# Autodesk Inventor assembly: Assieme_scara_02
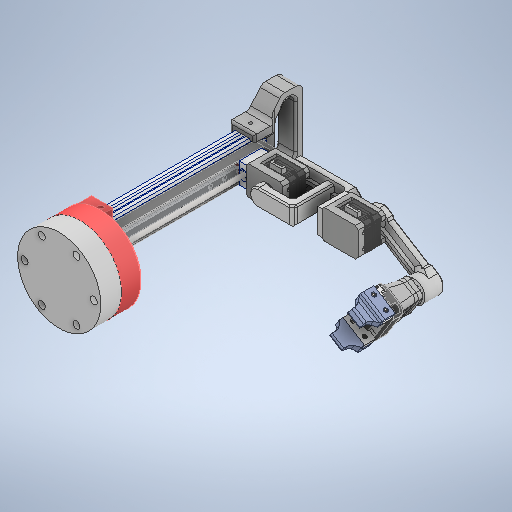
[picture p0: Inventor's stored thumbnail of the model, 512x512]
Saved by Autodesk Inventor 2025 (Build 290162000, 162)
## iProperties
Created: 2025-11
Part Number: Assieme_scara_02
Document SubType Name: Assembly
Designer: Ryzen5700u
Title: Assieme_scara_03.stp
Author: R5800u
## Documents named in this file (17)
- C:\Users\Ryzen5700u\Desktop\scara_06\Assieme_scara_05.iam
- C:\Users\Ryzen5700u\Desktop\scara_06\base1.ipt
- C:\Users\Ryzen5700u\Desktop\scara_06\blocco_motore1.ipt
- C:\Users\Ryzen5700u\Desktop\scara_06\AS 1420 - 1973 - M4 x 30.ipt
- C:\Users\Ryzen5700u\Desktop\scara_06\tslot 2040.ipt
- C:\Users\Ryzen5700u\Desktop\scara_06\Assieme_profilato.iam
- C:\Users\Ryzen5700u\Desktop\scara_06\maniglia.ipt
- C:\Users\Ryzen5700u\Desktop\scara_06\disco_120.ipt
- C:\Users\Ryzen5700u\Desktop\scara_06\gripper v3.iam
- C:\Users\Ryzen5700u\Desktop\scara_06\nema17_23mm.ipt
- C:\Users\Ryzen5700u\Desktop\scara_06\braccio_nema17.ipt
- C:\Users\Ryzen5700u\Desktop\scara_06\blocco_motore2.ipt
- C:\Users\Ryzen5700u\Desktop\scara_06\braccio_2_nema17.ipt
- C:\Users\Ryzen5700u\Desktop\scara_06\DUOPAN-DG.ipt
- C:\Users\Ryzen5700u\Documents\Inventor\Content Center Files\R2025\it-IT\BS 290 SKF(30)\BS 290 SKF - SKF 618_8.ipt
- C:\Users\Ryzen5700u\Desktop\scara_06\blocco_braccio_01.ipt
- C:\Users\Ryzen5700u\Documents\Inventor\Content Center Files\R2025\it-IT\ISO 14580_2011(E)\ISO 14580 M2,5x12-4.8.ipt
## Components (22 placed, 16 different names)
1. base1:1
2. blocco_motore1:1
3. AS 1420 - Metrico M4 x 30:1
4. AS 1420 - Metrico M4 x 30:2
5. AS 1420 - Metrico M4 x 30:3
6. AS 1420 - Metrico M4 x 30:4
7. tslot 2040:1 — Angolo:5
8. Assieme_profilato:1 [sub-assembly] — Coincidente:3, Angolo:1, Coincidente:4, Angolo:2
9. maniglia:1
10. disco_120:1
11. gripper v3:1 [sub-assembly] — Rotazionale:3, Angolo:3
12. nema17_23mm:1 — Coincidente:5, Allineato:1, Coincidente:6, Rotazionale:1
13. braccio_nema17:1
14. blocco_motore2:1 — Coincidente:9, Allineato:3, Allineato:4
15. nema17_23mm:2 — Rotazionale:2
16. braccio_2_nema17:1 — Rotazionale:2, Rotazionale:3, Angolo:3
17. DUOPAN-DG:1 — Rotazionale:4
18. BS 290 SKF 618/8:1 — Rotazionale:9
19. blocco_braccio_01:1 — Angolo:4, Rotazionale:9
20. Vite ISO 14580:2011(E) M2,5x12-4.8:1 — Rotazionale:6
21. Vite ISO 14580:2011(E) M2,5x12-4.8:2 — Rotazionale:7
22. Vite ISO 14580:2011(E) M2,5x12-4.8:3 — Rotazionale:8
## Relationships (21: RevoluteJoint 8, Mate 5, Angle 5, Flush 3)
- Coincidente:3 [Mate]: Assieme_profilato:1
- Angolo:1 [Angle]: Assieme_profilato:1
- Coincidente:4 [Mate]: Assieme_profilato:1
- Coincidente:5 [Mate]: nema17_23mm:1
- Allineato:1 [Flush]: nema17_23mm:1
- Coincidente:6 [Mate]: nema17_23mm:1
- Rotazionale:1 [RevoluteJoint]: nema17_23mm:1
- Coincidente:9 [Mate]: blocco_motore2:1
- Allineato:3 [Flush]: blocco_motore2:1
- Rotazionale:2 [RevoluteJoint]: nema17_23mm:2 ↔ braccio_2_nema17:1
- Angolo:2 [Angle]: Assieme_profilato:1
- Allineato:4 [Flush]: blocco_motore2:1
- Rotazionale:3 [RevoluteJoint]: gripper v3:1 ↔ braccio_2_nema17:1
- Angolo:3 [Angle]: gripper v3:1 ↔ braccio_2_nema17:1
- Rotazionale:4 [RevoluteJoint]: DUOPAN-DG:1
- Angolo:4 [Angle]: blocco_braccio_01:1
- Angolo:5 [Angle]: tslot 2040:1
- Rotazionale:6 [RevoluteJoint]: Vite ISO 14580:2011(E) M2,5x12-4.8:1
- Rotazionale:7 [RevoluteJoint]: Vite ISO 14580:2011(E) M2,5x12-4.8:2
- Rotazionale:8 [RevoluteJoint]: Vite ISO 14580:2011(E) M2,5x12-4.8:3
- Rotazionale:9 [RevoluteJoint]: BS 290 SKF 618/8:1 ↔ blocco_braccio_01:1
## Named parameters: d86_d83 = 0, d87_d81 = 0, d88_d79 = 21.15 mm
